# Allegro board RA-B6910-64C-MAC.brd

Outline 430 x 225 mm; copper layers: TOP, GND1, POWER1, SIG1, GND2, SIG2, GND3, SIG3, GND4, SIG4, GND5, SIG5, GND6, SIG6, GND7, SIG7, GND8, SIG8, GND9, SIG9, GND10, SIG10, GND11, POWER2, GND12, BOTTOM. Coordinates in mm from the lower left corner of the outline.
Outline path: 2,3 arc(0.59,3.59) 0,5 0,168.75 arc(0.59,170.16) 2,170.75 4.5,170.75 arc(5.21,171.04) 5.5,171.75 5.5,172.25 arc(5.21,172.96) 4.5,173.25 2,173.25 arc(0.59,173.84) 0,175.25 0,223 arc(0.59,224.41) 2,225 428,225 arc(429.41,224.41) 430,223 430,208.1 arc(429.41,206.69) 428,206.1 425.5,206.1 arc(424.79,205.81) 424.5,205.1 424.5,204.8 arc(424.79,204.09) 425.5,203.8 428,203.8 arc(429.41,203.21) 430,201.8 430,2 arc(429.41,0.59) 428,0 388,0 ; 2,3 385,3 ; 2,3 385,3 ; 385,3 arc(385.88,0.88) 388,0 ; 385,3 arc(385.88,0.88) 388,0 ; 389.3,72.5 arc(389.45,72.85) 389.8,73 392.8,73 arc(393.15,72.85) 393.3,72.5 393.3,68.5 arc(393.15,68.15) 392.8,68 389.8,68 arc(389.45,68.15) 389.3,68.5 389.3,72.5 ; 416.7,72.5 arc(416.85,72.85) 417.2,73 420.2,73 arc(420.55,72.85) 420.7,72.5 420.7,68.5 arc(420.55,68.15) 420.2,68 417.2,68 arc(416.85,68.15) 416.7,68.5 416.7,72.5

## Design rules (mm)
net group 56970_COREPLL_REFCLK_N: nets 56970_COREPLL_REFCLK_N N5117511
net group 56970_COREPLL_REFCLK_P: nets 56970_COREPLL_REFCLK_P N5117515
net group 56970_MISC_PLL_REFCLK_N: nets 56970_MISC_PLL_REFCLK_N N5121594
net group 56970_MISC_PLL_REFCLK_P: nets 56970_MISC_PLL_REFCLK_P N5121590
net group B50610_MDI_0N: nets B50610_MDI_0N B50610_MDI_1P
net group B50610_MDI_0P: nets B50610_MDI_0P B50610_MDI_1N
net group B50610_MDI_2N: nets B50610_MDI_2N B50610_MDI_3N
net group B50610_MDI_2P: nets B50610_MDI_2P B50610_MDI_3P
net group BMC_I2C_SDA: nets BMC_I2C_SDA N32265631
net group DIFFPAIR9: nets MAC_GND_SENSE MAC_VDD_SENSE
net group DIFFPAIR16: nets N32687490 N32687538
net group DIFFPAIR17: nets N32687488 N32687536
net group DIFFPAIR18: nets N32687486 N32687534
net group DIFFPAIR19: nets N32687454 N32687492
net group DIFFPAIR20: nets N32344332 N32344334
net group DIFFPAIR21: nets N32344144 N32344146
net group DIFFPAIR22: nets N32339133 N32340280
net group DIFFPAIR23: nets N32339113 N32339115
net group DIFFPAIR24: nets N32344318 N32344320
net group DIFFPAIR25: nets N32340551 N32340553
net group DIFFPAIR26: nets N32340547 N32340549
net group DIFFPAIR27: nets N32340543 N32340545
net group DIFFPAIR28: nets N5121846 N5121850
net group DIFFPAIR29: nets N6023779 N6023783
net group DIFFPAIR30: nets N6023843 N6023847
net group FC_PLL0_REFCLK_N: nets FC_PLL0_REFCLK_N N5126300
net group FC_PLL0_REFCLK_P: nets FC_PLL0_REFCLK_P N5126296
net group FC_PLL1_REFCLK_N: nets FC_PLL1_REFCLK_N N5126312
net group FC_PLL1_REFCLK_P: nets FC_PLL1_REFCLK_P N5126308
net group FC_PLL2_REFCLK_N: nets FC_PLL2_REFCLK_N N5126304
net group FC_PLL2_REFCLK_P: nets FC_PLL2_REFCLK_P N5126324
net group FC_PLL3_REFCLK_N: nets FC_PLL3_REFCLK_N N5126320
net group FC_PLL3_REFCLK_P: nets FC_PLL3_REFCLK_P N5126316
net group MC_TD1: nets MC_TDN1 MC_TDP1
net group MC_TD3: nets MC_TDN3 MC_TDP3
net group MDI_A: nets MDI_A+ MDI_A-
net group MDI_B: nets MDI_B+ MDI_B-
net group MDI_C: nets MDI_C+ MDI_C-
net group MDI_D: nets MDI_D+ MDI_D-
net group USB: nets USB0_DM USB0_DP
net group 25G: nets FC0_RDN0 FC0_RDN1 FC0_RDN2 FC0_RDN3 FC0_RDP0 FC0_RDP1 FC0_RDP2 FC0_RDP3 FC0_TDN0 FC0_TDN1 FC0_TDN2 FC0_TDN3 FC0_TDP0 FC0_TDP1 FC0_TDP2 FC0_TDP3 FC1_RDN0 FC1_RDN1 FC1_RDN2 FC1_RDN3 FC1_RDP0 FC1_RDP1 FC1_RDP2 FC1_RDP3 FC1_TDN0 FC1_TDN1 FC1_TDN2 FC1_TDN3 FC1_TDP0 FC1_TDP1 FC1_TDP2 FC1_TDP3 FC2_RDN0 FC2_RDN1 FC2_RDN2 FC2_RDN3 FC2_RDP0 FC2_RDP1 FC2_RDP2 FC2_RDP3 FC2_TDN0 FC2_TDN1 FC2_TDN2 FC2_TDN3 FC2_TDP0 FC2_TDP1 FC2_TDP2 FC2_TDP3 FC3_RDN0 FC3_RDN1 FC3_RDN2 FC3_RDN3 FC3_RDP0 FC3_RDP1 FC3_RDP2 FC3_RDP3 FC3_TDN0 FC3_TDN1 FC3_TDN2 FC3_TDN3 FC3_TDP0 FC3_TDP1 FC3_TDP2 FC3_TDP3 FC4_RDN0 FC4_RDN1 FC4_RDN2 FC4_RDN3 FC4_RDP0 FC4_RDP1 FC4_RDP2 FC4_RDP3 FC4_TDN0 FC4_TDN1 FC4_TDN2 FC4_TDN3 FC4_TDP0 FC4_TDP1 FC4_TDP2 FC4_TDP3 FC5_RDN0 FC5_RDN1 FC5_RDN2 FC5_RDN3 FC5_RDP0 FC5_RDP1 FC5_RDP2 FC5_RDP3 FC5_TDN0 FC5_TDN1 FC5_TDN2 FC5_TDN3 FC5_TDP0 FC5_TDP1 FC5_TDP2 FC5_TDP3 FC6_RDN0 FC6_RDN1 FC6_RDN2 FC6_RDN3 FC6_RDP0 FC6_RDP1 FC6_RDP2 FC6_RDP3 FC6_TDN0 FC6_TDN1 FC6_TDN2 FC6_TDN3 FC6_TDP0 FC6_TDP1 FC6_TDP2 FC6_TDP3 FC7_RDN0 FC7_RDN1 FC7_RDN2 FC7_RDN3 FC7_RDP0 FC7_RDP1 FC7_RDP2 FC7_RDP3 FC7_TDN0 FC7_TDN1 FC7_TDN2 FC7_TDN3 FC7_TDP0 FC7_TDP1 FC7_TDP2 FC7_TDP3 FC8_RDN0 FC8_RDN1 FC8_RDN2 FC8_RDN3 FC8_RDP0 FC8_RDP1 FC8_RDP2 FC8_RDP3 FC8_TDN0 FC8_TDN1 FC8_TDN2 FC8_TDN3 FC8_TDP0 FC8_TDP1 FC8_TDP2 FC8_TDP3 FC9_RDN0 FC9_RDN1 FC9_RDN2 FC9_RDN3 FC9_RDP0 FC9_RDP1 FC9_RDP2 FC9_RDP3 FC9_TDN0 FC9_TDN1 FC9_TDN2 FC9_TDN3 FC9_TDP0 FC9_TDP1 FC9_TDP2 FC9_TDP3 FC10_RDN0 FC10_RDN1 FC10_RDN2 FC10_RDN3 FC10_RDP0 FC10_RDP1 FC10_RDP2 FC10_RDP3 FC10_TDN0 FC10_TDN1 FC10_TDN2 FC10_TDN3 FC10_TDP0 FC10_TDP1 FC10_TDP2 FC10_TDP3 FC11_RDN0 FC11_RDN1 FC11_RDN2 FC11_RDN3 FC11_RDP0 FC11_RDP1 FC11_RDP2 FC11_RDP3 FC11_TDN0 FC11_TDN1 FC11_TDN2 FC11_TDN3 FC11_TDP0 FC11_TDP1 FC11_TDP2 FC11_TDP3 FC12_RDN0 FC12_RDN1 FC12_RDN2 FC12_RDN3 FC12_RDP0 FC12_RDP1 FC12_RDP2 FC12_RDP3 FC12_TDN0 FC12_TDN1 FC12_TDN2 FC12_TDN3 FC12_TDP0 FC12_TDP1 FC12_TDP2 FC12_TDP3 FC13_RDN0 FC13_RDN1 FC13_RDN2 FC13_RDN3 FC13_RDP0 FC13_RDP1 FC13_RDP2 FC13_RDP3 FC13_TDN0 FC13_TDN1 FC13_TDN2 FC13_TDN3 FC13_TDP0 FC13_TDP1 FC13_TDP2 FC13_TDP3 FC14_RDN0 FC14_RDN1 FC14_RDN2 FC14_RDN3 FC14_RDP0 FC14_RDP1 FC14_RDP2 FC14_RDP3 FC14_TDN0 FC14_TDN1 FC14_TDN2 FC14_TDN3 FC14_TDP0 FC14_TDP1 FC14_TDP2 FC14_TDP3 FC15_RDN0 FC15_RDN1 FC15_RDN2 FC15_RDN3 FC15_RDP0 FC15_RDP1 FC15_RDP2 FC15_RDP3 FC15_TDN0 FC15_TDN1 FC15_TDN2 FC15_TDN3 FC15_TDP0 FC15_TDP1 FC15_TDP2 FC15_TDP3 FC16_RDN0 FC16_RDN1 FC16_RDN2 FC16_RDN3 FC16_RDP0 FC16_RDP1 FC16_RDP2 FC16_RDP3 FC16_TDN0 FC16_TDN1 FC16_TDN2 FC16_TDN3 FC16_TDP0 FC16_TDP1 FC16_TDP2 FC16_TDP3 FC17_RDN0 FC17_RDN1 FC17_RDN2 FC17_RDN3 FC17_RDP0 FC17_RDP1 FC17_RDP2 FC17_RDP3 FC17_TDN0 FC17_TDN1 FC17_TDN2 FC17_TDN3 FC17_TDP0 FC17_TDP1 FC17_TDP2 FC17_TDP3 FC18_RDN0 FC18_RDN1 FC18_RDN2 FC18_RDN3 FC18_RDP0 FC18_RDP1 FC18_RDP2 FC18_RDP3 FC18_TDN0 FC18_TDN1 FC18_TDN2 FC18_TDN3 FC18_TDP0 FC18_TDP1 FC18_TDP2 FC18_TDP3 FC19_RDN0 FC19_RDN1 FC19_RDN2 FC19_RDN3 FC19_RDP0 FC19_RDP1 FC19_RDP2 FC19_RDP3 FC19_TDN0 FC19_TDN1 FC19_TDN2 FC19_TDN3 FC19_TDP0 FC19_TDP1 FC19_TDP2 FC19_TDP3 FC20_RDN0 FC20_RDN1 FC20_RDN2 FC20_RDN3 FC20_RDP0 FC20_RDP1 FC20_RDP2 FC20_RDP3 FC20_TDN0 FC20_TDN1 FC20_TDN2 FC20_TDN3 FC20_TDP0 FC20_TDP1 FC20_TDP2 FC20_TDP3 FC21_RDN0 FC21_RDN1 FC21_RDN2 FC21_RDN3 FC21_RDP0 FC21_RDP1 FC21_RDP2 FC21_RDP3 FC21_TDN0 FC21_TDN1 FC21_TDN2 FC21_TDN3 FC21_TDP0 FC21_TDP1 FC21_TDP2 FC21_TDP3 FC22_RDN0 FC22_RDN1 FC22_RDN2 FC22_RDN3 FC22_RDP0 FC22_RDP1 FC22_RDP2 FC22_RDP3 FC22_TDN0 FC22_TDN1 FC22_TDN2 FC22_TDN3 FC22_TDP0 FC22_TDP1 FC22_TDP2 FC22_TDP3 FC23_RDN0 FC23_RDN1 FC23_RDN2 FC23_RDN3 FC23_RDP0 FC23_RDP1 FC23_RDP2 FC23_RDP3 FC23_TDN0 FC23_TDN1 FC23_TDN2 FC23_TDN3 FC23_TDP0 FC23_TDP1 FC23_TDP2 FC23_TDP3 FC24_RDN0 FC24_RDN1 FC24_RDN2 FC24_RDN3 FC24_RDP0 FC24_RDP1 FC24_RDP2 FC24_RDP3 FC24_TDN0 FC24_TDN1 FC24_TDN2 FC24_TDN3 FC24_TDP0 FC24_TDP1 FC24_TDP2 FC24_TDP3 FC25_RDN0 FC25_RDN1 FC25_RDN2 FC25_RDN3 FC25_RDP0 FC25_RDP1 FC25_RDP2 FC25_RDP3 FC25_TDN0 FC25_TDN1 FC25_TDN2 FC25_TDN3 FC25_TDP0 FC25_TDP1 FC25_TDP2 FC25_TDP3 FC26_RDN0 FC26_RDN1 FC26_RDN2 FC26_RDN3 FC26_RDP0 FC26_RDP1 FC26_RDP2 FC26_RDP3 FC26_TDN0 FC26_TDN1 FC26_TDN2 FC26_TDN3 FC26_TDP0 FC26_TDP1 FC26_TDP2 FC26_TDP3 FC27_RDN0 FC27_RDN1 FC27_RDN2 FC27_RDN3 FC27_RDP0 FC27_RDP1 FC27_RDP2 FC27_RDP3 FC27_TDN0 FC27_TDN1 FC27_TDN2 FC27_TDN3 FC27_TDP0 FC27_TDP1 FC27_TDP2 FC27_TDP3 FC28_RDN0 FC28_RDN1 FC28_RDN2 FC28_RDN3 FC28_RDP0 FC28_RDP1 FC28_RDP2 FC28_RDP3 FC28_TDN0 FC28_TDN1 FC28_TDN2 FC28_TDN3 FC28_TDP0 FC28_TDP1 FC28_TDP2 FC28_TDP3 FC29_RDN0 FC29_RDN1 FC29_RDN2 FC29_RDN3 FC29_RDP0 FC29_RDP1 FC29_RDP2 FC29_RDP3 FC29_TDN0 FC29_TDN1 FC29_TDN2 FC29_TDN3 FC29_TDP0 FC29_TDP1 FC29_TDP2 FC29_TDP3 FC30_RDN0 FC30_RDN1 FC30_RDN2 FC30_RDN3 FC30_RDP0 FC30_RDP1 FC30_RDP2 FC30_RDP3 FC30_TDN0 FC30_TDN1 FC30_TDN2 FC30_TDN3 FC30_TDP0 FC30_TDP1 FC30_TDP2 FC30_TDP3 FC31_RDN0 FC31_RDN1 FC31_RDN2 FC31_RDN3 FC31_RDP0 FC31_RDP1 FC31_RDP2 FC31_RDP3 FC31_TDN0 FC31_TDN1 FC31_TDN2 FC31_TDN3 FC31_TDP0 FC31_TDP1 FC31_TDP2 FC31_TDP3 FC32_RDN0 FC32_RDN1 FC32_RDN2 FC32_RDN3 FC32_RDP0 FC32_RDP1 FC32_RDP2 FC32_RDP3 FC32_TDN0 FC32_TDN1 FC32_TDN2 FC32_TDN3 FC32_TDP0 FC32_TDP1 FC32_TDP2 FC32_TDP3 FC33_RDN0 FC33_RDN1 FC33_RDN2 FC33_RDN3 FC33_RDP0 FC33_RDP1 FC33_RDP2 FC33_RDP3 FC33_TDN0 FC33_TDN1 FC33_TDN2 FC33_TDN3 FC33_TDP0 FC33_TDP1 FC33_TDP2 FC33_TDP3 FC34_RDN0 FC34_RDN1 FC34_RDN2 FC34_RDN3 FC34_RDP0 FC34_RDP1 FC34_RDP2 FC34_RDP3 FC34_TDN0 FC34_TDN1 FC34_TDN2 FC34_TDN3 FC34_TDP0 FC34_TDP1 FC34_TDP2 FC34_TDP3 FC35_RDN0 FC35_RDN1 FC35_RDN2 FC35_RDN3 FC35_RDP0 FC35_RDP1 FC35_RDP2 FC35_RDP3 FC35_TDN0 FC35_TDN1 FC35_TDN2 FC35_TDN3 FC35_TDP0 FC35_TDP1 FC35_TDP2 FC35_TDP3 FC36_RDN0 FC36_RDN1 FC36_RDN2 FC36_RDN3 FC36_RDP0 FC36_RDP1 FC36_RDP2 FC36_RDP3 FC36_TDN0 FC36_TDN1 FC36_TDN2 FC36_TDN3 FC36_TDP0 FC36_TDP1 FC36_TDP2 FC36_TDP3 FC37_RDN0 FC37_RDN1 FC37_RDN2 FC37_RDN3 FC37_RDP0 FC37_RDP1 FC37_RDP2 FC37_RDP3 FC37_TDN0 FC37_TDN1 FC37_TDN2 FC37_TDN3 FC37_TDP0 FC37_TDP1 FC37_TDP2 FC37_TDP3 FC38_RDN0 FC38_RDN1 FC38_RDN2 FC38_RDN3 FC38_RDP0 FC38_RDP1 FC38_RDP2 FC38_RDP3 FC38_TDN0 FC38_TDN1 FC38_TDN2 FC38_TDN3 FC38_TDP0 FC38_TDP1 FC38_TDP2 FC38_TDP3 FC39_RDN0 FC39_RDN1 FC39_RDN2 FC39_RDN3 FC39_RDP0 FC39_RDP1 FC39_RDP2 FC39_RDP3 FC39_TDN0 FC39_TDN1 FC39_TDN2 FC39_TDN3 FC39_TDP0 FC39_TDP1 FC39_TDP2 FC39_TDP3 FC40_RDN0 FC40_RDN1 FC40_RDN2 FC40_RDN3 FC40_RDP0 FC40_RDP1 FC40_RDP2 FC40_RDP3 FC40_TDN0 FC40_TDN1 FC40_TDN2 FC40_TDN3 FC40_TDP0 FC40_TDP1 FC40_TDP2 FC40_TDP3 FC41_RDN0 FC41_RDN1 FC41_RDN2 FC41_RDN3 FC41_RDP0 FC41_RDP1 FC41_RDP2 FC41_RDP3 FC41_TDN0 FC41_TDN1 FC41_TDN2 FC41_TDN3 FC41_TDP0 FC41_TDP1 FC41_TDP2 FC41_TDP3 FC42_RDN0 FC42_RDN1 FC42_RDN2 FC42_RDN3 FC42_RDP0 FC42_RDP1 FC42_RDP2 FC42_RDP3 FC42_TDN0 FC42_TDN1 FC42_TDN2 FC42_TDN3 FC42_TDP0 FC42_TDP1 FC42_TDP2 FC42_TDP3 FC43_RDN0 FC43_RDN1 FC43_RDN2 FC43_RDN3 FC43_RDP0 FC43_RDP1 FC43_RDP2 FC43_RDP3 FC43_TDN0 FC43_TDN1 FC43_TDN2 FC43_TDN3 FC43_TDP0 FC43_TDP1 FC43_TDP2 FC43_TDP3 FC44_RDN0 FC44_RDN1 FC44_RDN2 FC44_RDN3 FC44_RDP0 FC44_RDP1 FC44_RDP2 FC44_RDP3 FC44_TDN0 FC44_TDN1 FC44_TDN2 FC44_TDN3 FC44_TDP0 FC44_TDP1 FC44_TDP2 FC44_TDP3 FC45_RDN0 FC45_RDN1 FC45_RDN2 FC45_RDN3 FC45_RDP0 FC45_RDP1 FC45_RDP2 FC45_RDP3 FC45_TDN0 FC45_TDN1 FC45_TDN2 FC45_TDN3 FC45_TDP0 FC45_TDP1 FC45_TDP2 FC45_TDP3 FC46_RDN0 FC46_RDN1 FC46_RDN2 FC46_RDN3 FC46_RDP0 FC46_RDP1 FC46_RDP2 FC46_RDP3 FC46_TDN0 FC46_TDN1 FC46_TDN2 FC46_TDN3 FC46_TDP0 FC46_TDP1 FC46_TDP2 FC46_TDP3 FC47_RDN0 FC47_RDN1 FC47_RDN2 FC47_RDN3 FC47_RDP0 FC47_RDP1 FC47_RDP2 FC47_RDP3 FC47_TDN0 FC47_TDN1 FC47_TDN2 FC47_TDN3 FC47_TDP0 FC47_TDP1 FC47_TDP2 FC47_TDP3 FC48_RDN0 FC48_RDN1 FC48_RDN2 FC48_RDN3 FC48_RDP0 FC48_RDP1 FC48_RDP2 FC48_RDP3 FC48_TDN0 FC48_TDN1 FC48_TDN2 FC48_TDN3 FC48_TDP0 FC48_TDP1 FC48_TDP2 FC48_TDP3 FC49_RDN0 FC49_RDN1 FC49_RDN2 FC49_RDN3 FC49_RDP0 FC49_RDP1 FC49_RDP2 FC49_RDP3 FC49_TDN0 FC49_TDN1 FC49_TDN2 FC49_TDN3 FC49_TDP0 FC49_TDP1 FC49_TDP2 FC49_TDP3 FC50_RDN0 FC50_RDN1 FC50_RDN2 FC50_RDN3 FC50_RDP0 FC50_RDP1 FC50_RDP2 FC50_RDP3 FC50_TDN0 FC50_TDN1 FC50_TDN2 FC50_TDN3 FC50_TDP0 FC50_TDP1 FC50_TDP2 FC50_TDP3 FC51_RDN0 FC51_RDN1 FC51_RDN2 FC51_RDN3 FC51_RDP0 FC51_RDP1 FC51_RDP2 FC51_RDP3 FC51_TDN0 FC51_TDN1 FC51_TDN2 FC51_TDN3 FC51_TDP0 FC51_TDP1 FC51_TDP2 FC51_TDP3 FC52_RDN0 FC52_RDN1 FC52_RDN2 FC52_RDN3 FC52_RDP0 FC52_RDP1 FC52_RDP2 FC52_RDP3 FC52_TDN0 FC52_TDN1 FC52_TDN2 FC52_TDN3 FC52_TDP0 FC52_TDP1 FC52_TDP2 FC52_TDP3 FC53_RDN0 FC53_RDN1 FC53_RDN2 FC53_RDN3 FC53_RDP0 FC53_RDP1 FC53_RDP2 FC53_RDP3 FC53_TDN0 FC53_TDN1 FC53_TDN2 FC53_TDN3 FC53_TDP0 FC53_TDP1 FC53_TDP2 FC53_TDP3 FC54_RDN0 FC54_RDN1 FC54_RDN2 FC54_RDN3 FC54_RDP0 FC54_RDP1 FC54_RDP2 FC54_RDP3 FC54_TDN0 FC54_TDN1 FC54_TDN2 FC54_TDN3 FC54_TDP0 FC54_TDP1 FC54_TDP2 FC54_TDP3 FC55_RDN0 FC55_RDN1 FC55_RDN2 FC55_RDN3 FC55_RDP0 FC55_RDP1 FC55_RDP2 FC55_RDP3 FC55_TDN0 FC55_TDN1 FC55_TDN2 FC55_TDN3 FC55_TDP0 FC55_TDP1 FC55_TDP2 FC55_TDP3 FC56_RDN0 FC56_RDN1 FC56_RDN2 FC56_RDN3 FC56_RDP0 FC56_RDP1 FC56_RDP2 FC56_RDP3 FC56_TDN0 FC56_TDN1 FC56_TDN2 FC56_TDN3 FC56_TDP0 FC56_TDP1 FC56_TDP2 FC56_TDP3 FC57_RDN0 FC57_RDN1 FC57_RDN2 FC57_RDN3 FC57_RDP0 FC57_RDP1 FC57_RDP2 FC57_RDP3 FC57_TDN0 FC57_TDN1 FC57_TDN2 FC57_TDN3 FC57_TDP0 FC57_TDP1 FC57_TDP2 FC57_TDP3 FC58_RDN0 FC58_RDN1 FC58_RDN2 FC58_RDN3 FC58_RDP0 FC58_RDP1 FC58_RDP2 FC58_RDP3 FC58_TDN0 FC58_TDN1 FC58_TDN2 FC58_TDN3 FC58_TDP0 FC58_TDP1 FC58_TDP2 FC58_TDP3 FC59_RDN0 FC59_RDN1 FC59_RDN2 FC59_RDN3 FC59_RDP0 FC59_RDP1 FC59_RDP2 FC59_RDP3 FC59_TDN0 FC59_TDN1 FC59_TDN2 FC59_TDN3 FC59_TDP0 FC59_TDP1 FC59_TDP2 FC59_TDP3 FC60_RDN0 FC60_RDN1 FC60_RDN2 FC60_RDN3 FC60_RDP0 FC60_RDP1 FC60_RDP2 FC60_RDP3 FC60_TDN0 FC60_TDN1 FC60_TDN2 FC60_TDN3 FC60_TDP0 FC60_TDP1 FC60_TDP2 FC60_TDP3 FC61_RDN0 FC61_RDN1 FC61_RDN2 FC61_RDN3 FC61_RDP0 FC61_RDP1 FC61_RDP2 FC61_RDP3 FC61_TDN0 FC61_TDN1 FC61_TDN2 FC61_TDN3 FC61_TDP0 FC61_TDP1 FC61_TDP2 FC61_TDP3 FC62_RDN0 FC62_RDN1 FC62_RDN2 FC62_RDN3 FC62_RDP0 FC62_RDP1 FC62_RDP2 FC62_RDP3 FC62_TDN0 FC62_TDN1 FC62_TDN2 FC62_TDN3 FC62_TDP0 FC62_TDP1 FC62_TDP2 FC62_TDP3 FC63_RDN0 FC63_RDN1 FC63_RDN2 FC63_RDN3 FC63_RDP0 FC63_RDP1 FC63_RDP2 FC63_RDP3 FC63_TDN0 FC63_TDN1 FC63_TDN2 FC63_TDN3 FC63_TDP0 FC63_TDP1 FC63_TDP2 FC63_TDP3 FC_LOS0 FC_LOS1 FC_LOS2 FC_LOS3 FC_LOS4 FC_LOS5 FC_LOS6 FC_LOS7 FC_LOS8 FC_LOS9 FC_LOS10 FC_LOS11 FC_LOS12 FC_LOS13 FC_LOS14 FC_LOS15 FC_LOS16 FC_LOS17 FC_LOS18 FC_LOS19 FC_LOS20 FC_LOS21 FC_LOS22 FC_LOS23 FC_LOS24 FC_LOS25 FC_LOS26 FC_LOS27 FC_LOS28 FC_LOS29 FC_LOS30 FC_LOS31 FC_LOS32 FC_LOS33 FC_LOS34 FC_LOS35 FC_LOS36 FC_LOS37 FC_LOS38 FC_LOS39 FC_LOS40 FC_LOS41 FC_LOS42 FC_LOS43 FC_LOS44 FC_LOS45 FC_LOS46 FC_LOS47 FC_LOS48 FC_LOS49 FC_LOS50 FC_LOS51 FC_LOS52 FC_LOS53 FC_LOS54 FC_LOS55 FC_LOS56 FC_LOS57 FC_LOS58 FC_LOS59 FC_LOS60 FC_LOS61 FC_LOS62 FC_LOS63
net group CLK-DIFF: nets 56970_PCIE_PLL_REFCLK_N 56970_PCIE_PLL_REFCLK_P MASTER_CPLD_CLK_N MASTER_CPLD_CLK_P SECOND_CPLD_CLK_N SECOND_CPLD_CLK_P
net group CPU_I2C_SDA: nets CPU_I2C_SDA N24037211 N24037257 N24037299 N24037469 N24044300 N24045758 N24045803 N24045845
net group KR: nets MAC_MC_RDN0 MAC_MC_RDN2 MAC_MC_RDP0 MAC_MC_RDP2 MC_RDN0 MC_RDN2 MC_RDP0 MC_RDP2 MC_TDN0 MC_TDN2 MC_TDP0 MC_TDP2
net group PCIE: nets MAC_PCIE_RXN0 MAC_PCIE_RXN1 MAC_PCIE_RXN2 MAC_PCIE_RXN3 MAC_PCIE_RXP0 MAC_PCIE_RXP1 MAC_PCIE_RXP2 MAC_PCIE_RXP3 MAC_PCIE_TXN0 MAC_PCIE_TXN1 MAC_PCIE_TXN2 MAC_PCIE_TXN3 MAC_PCIE_TXP0 MAC_PCIE_TXP1 MAC_PCIE_TXP2 MAC_PCIE_TXP3 N26921640 N26921643 N26921646 N26921649 N26921652 N26921655 N26921658 N26921661
net group VDD1.2V: nets N24368040
nets with their own width: min track width 0.381; nets GND

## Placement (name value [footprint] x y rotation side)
C1  X  [C0402]  260.29 170.3 90 top
C2  0.1uF/25V  [C0402]  205.07 156.35 90 bottom
C3  0.1uF/25V  [C0402]  204.05 158.35 90 bottom
C4  0.1uF/25V  [C0402]  205.04 154.35 270 bottom
C5  103  [C0402]  179.13 191.13 270 top
C6  103  [C0402]  178.12 191.13 270 top
C7  103  [C0402]  182.56 186.81 270 top
C8  103  [C0402]  181.55 186.81 270 top
C9  103  [C0402]  250 138.43 180 top
C10  103  [C0402]  250 137.28 180 top
C11  104  [C0603]  37.27 205.99 90 bottom
C12  10uF/25V  [C0805]  17.84 205.74 90 bottom
C13  1uF/25V  [C0805]  35.12 205.86 90 bottom
C14  33uF/10V  [C1206]  394.4 24.76 0 top
C17  103  [C0402]  155.51 128.27 0 top
C18  103  [C0402]  155.51 129.28 0 top
C19  103  [C0402]  247.84 143.51 270 top
C20  103  [C0402]  246.82 143.51 270 top
C21  5.6P  [C0402]  403.16 194.43 0 top
C27  0.1uF/25V  [C0402]  205.07 158.35 90 bottom
C28  0.1uF/25V  [C0402]  210.07 158.34 90 bottom
C29  0.1uF/25V  [C0402]  205.56 120.84 180 bottom
C30  0.1uF/25V  [C0402]  207.55 123.82 180 bottom
C49  0.1uF/25V  [C0402]  215.56 159.85 0 bottom
C50  0.1uF/25V  [C0402]  215.54 122.85 0 bottom
C51  0.1uF/25V  [C0402]  215.55 115.81 180 bottom
C52  0.1uF/25V  [C0402]  187.05 154.33 270 bottom
C53  0.1uF/25V  [C0402]  185.05 156.33 270 bottom
C54  1uF/25V  [C0402]  215.55 114.81 180 bottom
C74  0.1uF/25V  [C0402]  219.65 200.15 90 top
C75  22uF/6.3V  [C0603]  152.59 133.09 270 top
C76  0.1uF/25V  [C0402]  178.63 137.72 0 bottom
C79  22uF/6.3V  [C0603]  176.72 191.64 90 top
C80  0.1uF/25V  [C0402]  199.54 157.83 0 bottom
C82  0.1uF/25V  [C0402]  235.65 145.54 90 top
C83  22uF/6.3V  [C0603]  235.65 137.79 270 top
C84  0.1uF/25V  [C0402]  215.55 138.82 180 bottom
C86  0.1uF/25V  [C0402]  161.86 191.64 270 top
C87  22uF/6.3V  [C0603]  219.65 192.66 270 top
C88  0.1uF/25V  [C0402]  204.05 156.35 90 bottom
C90  0.1uF/25V  [C0402]  181.29 178.43 270 top
C91  22uF/6.3V  [C0603]  185.48 179.07 90 top
C92  0.1uF/25V  [C0402]  178.57 153.85 180 bottom
C93  0.1uF/25V  [C0402]  195.55 151.82 180 bottom
C94  0.1uF/25V  [C0402]  193.55 146.82 180 bottom
C95  0.1uF/25V  [C0402]  217.57 152.83 0 bottom
C96  0.1uF/25V  [C0402]  178.56 128.83 0 bottom
C97  0.1uF/25V  [C0402]  215.55 129.82 180 bottom
C98  0.1uF/25V  [C0402]  197.54 127.83 180 bottom
C99  0.1uF/25V  [C0402]  197.54 128.83 180 bottom
C100  0.1uF/25V  [C0402]  185.36 198.25 90 top
C101  22uF/6.3V  [C0603]  185.1 192.4 270 top
C102  0.1uF/25V  [C0402]  191.55 153.82 180 bottom
C103  0.1uF/25V  [C0402]  189.05 154.33 90 bottom
C108  102  [C0402]  387.92 213.61 270 top
C109  0.1uF/25V  [C0402]  389.14 213.61 270 top
C110  33uF/10V  [C1206]  384.29 212.94 270 bottom
C111  0.1uF/25V  [C0402]  423.1 129.16 0 top
C112  0.1uF/25V  [C0402]  57.21 106.04 0 top
C113  0.1uF/25V  [C0402]  22.54 100.96 0 top
C114  0.1uF/25V  [C0402]  265.29 181.4 270 top
C115  0.1uF/25V  [C0402]  411.34 116.58 180 bottom
C116  0.1uF/25V  [C0402]  10.66 100.96 180 bottom
C117  0.1uF/25V  [C0402]  45.33 106.04 180 bottom
C118  0.1uF/25V  [C0402]  411.34 128.1 180 bottom
C119  0.1uF/25V  [C0402]  423.1 116.58 0 top
C203  22uF/6.3V  [C0603]  236.66 111 180 top
C204  0.1uF/25V  [C0402]  211.56 110.86 180 bottom
C205  0.1uF/25V  [C0402]  205.57 107.84 180 bottom
C206  0.1uF/25V  [C0402]  205.57 106.84 180 bottom
C207  0.1uF/25V  [C0402]  229.56 119.83 0 bottom
C209  0.1uF/25V  [C0402]  230.57 109.84 0 bottom
C212  0.1uF/25V  [C0402]  227.54 125.85 0 bottom
C213  0.1uF/25V  [C0402]  199.56 110.86 0 bottom
C215  0.1uF/25V  [C0402]  199.56 109.84 180 bottom
C216  0.1uF/25V  [C0402]  226.53 115.84 0 bottom
C219  0.1uF/25V  [C0402]  229.55 133.82 0 bottom
C221  0.1uF/25V  [C0402]  231.2 177.54 270 top
C226  0.1uF/25V  [C0402]  207.02 170.38 270 bottom
C227  0.1uF/25V  [C0402]  211.06 167.33 270 bottom
C247  0.1uF/25V  [C0402]  199.03 170.33 270 bottom
C274  22uF/6.3V  [C0603]  153.61 173.06 90 top
C275  0.1uF/25V  [C0402]  182.05 154.33 90 bottom
C276  0.1uF/25V  [C0402]  155.26 165.99 90 top
C277  22uF/6.3V  [C0603]  157.16 158.11 270 top
C278  0.1uF/25V  [C0402]  181.54 152.83 0 bottom
C279  0.1uF/25V  [C0402]  154.24 165.99 90 top
C280  22uF/6.3V  [C0603]  154.88 158.11 270 top
C281  0.1uF/25V  [C0402]  181.54 149.83 0 bottom
C282  0.1uF/25V  [C0402]  141.67 150.31 90 bottom
C283  22uF/6.3V  [C0603]  157.16 145.79 270 top
C284  0.1uF/25V  [C0402]  181.53 146.83 180 bottom
C297  10uF/25V  [C0805]  253.84 209.78 270 top
C298  10uF/25V  [C0805]  256.38 209.78 270 top
C299  104  [C0603]  258.38 209.67 270 top
C300  104  [C0603]  257.54 216.1 90 bottom
C301  X  [C0603]  266.94 215.31 180 top
C302  1uF/25V  [C0402]  267.02 216.84 0 top
C303  103  [C0402]  267.02 218.11 0 top
C305  22uF/6.3V  [C0603]  240.37 208.56 270 top
C306  22uF/6.3V  [C0603]  238.85 208.56 270 top
C307  1uF/25V  [C0402]  242.89 208.53 270 top
C308  0.1uF/25V  [C0402]  241.74 208.53 270 top
C349  22uF/6.3V  [C0603]  214.82 192.66 270 top
C350  0.1uF/25V  [C0402]  213.58 153.85 0 bottom
C351  0.1uF/25V  [C0402]  222.06 200.15 90 top
C352  22uF/6.3V  [C0603]  229.3 192.66 270 top
C389  0.1uF/25V  [C0402]  170.53 157.84 0 bottom
C391  0.1uF/25V  [C0402]  168.52 160.84 0 bottom
C393  0.1uF/25V  [C0402]  168.52 156.84 180 bottom
C395  0.1uF/25V  [C0402]  168.52 158.85 0 bottom
C396  0.1uF/25V  [C0402]  176.58 157.84 0 bottom
C397  0.1uF/25V  [C0402]  177.55 154.84 0 bottom
C398  0.1uF/25V  [C0402]  172.53 157.84 0 bottom
C399  0.1uF/25V  [C0402]  170.52 158.85 0 bottom
C400  0.1uF/25V  [C0402]  174.53 160.84 0 bottom
C401  0.1uF/25V  [C0402]  172.53 160.84 0 bottom
C402  0.1uF/25V  [C0402]  166.56 154.86 0 bottom
C403  0.1uF/25V  [C0402]  171.54 151.82 0 bottom
C404  0.1uF/25V  [C0402]  168.57 154.84 0 bottom
C405  0.1uF/25V  [C0402]  174.53 157.84 0 bottom
C406  0.1uF/25V  [C0402]  170.57 154.84 0 bottom
C407  0.1uF/25V  [C0402]  183.06 160.32 270 bottom
C408  0.1uF/25V  [C0402]  165.57 152.83 180 bottom
C409  0.1uF/25V  [C0402]  172.58 154.85 0 bottom
C410  0.1uF/25V  [C0402]  187.04 161.36 90 bottom
C411  0.1uF/25V  [C0402]  189.55 160.83 0 bottom
C412  0.1uF/25V  [C0402]  192.56 159.86 0 bottom
C413  0.1uF/25V  [C0402]  176.58 160.84 0 bottom
C414  0.1uF/25V  [C0402]  141.77 162.51 90 bottom
C415  22uF/6.3V  [C0603]  154.98 157.53 0 bottom
C416  0.1uF/25V  [C0402]  186.04 161.36 270 bottom
C417  0.1uF/25V  [C0402]  186.07 164.29 90 bottom
C418  0.1uF/25V  [C0402]  187.57 166.85 0 bottom
C419  0.1uF/25V  [C0402]  190.58 164.83 0 bottom
C420  0.1uF/25V  [C0402]  166.54 166.86 0 bottom
C421  0.1uF/25V  [C0402]  166.56 162.84 0 bottom
C422  0.1uF/25V  [C0402]  165.54 164.84 0 bottom
C423  0.1uF/25V  [C0402]  183.05 164.32 270 bottom
C424  0.1uF/25V  [C0402]  183.05 162.32 90 bottom
C425  0.1uF/25V  [C0402]  183.06 166.32 90 bottom
C426  0.1uF/25V  [C0402]  180.05 162.33 90 bottom
C427  0.1uF/25V  [C0402]  181.04 164.34 90 bottom
C428  0.1uF/25V  [C0402]  180.04 167.36 90 bottom
C429  0.1uF/25V  [C0402]  179.04 162.32 90 bottom
C430  0.1uF/25V  [C0402]  179.04 164.33 90 bottom
C431  0.1uF/25V  [C0402]  179.05 167.33 90 bottom
C432  0.1uF/25V  [C0402]  176.56 165.86 0 bottom
C433  0.1uF/25V  [C0402]  173.56 164.82 0 bottom
C434  0.1uF/25V  [C0402]  176.56 164.83 0 bottom
C435  0.1uF/25V  [C0402]  192.56 162.86 0 bottom
C436  0.1uF/25V  [C0402]  196.04 164.35 90 bottom
C437  0.1uF/25V  [C0402]  189.05 162.34 90 bottom
C438  0.1uF/25V  [C0402]  192.56 165.86 0 bottom
C439  0.1uF/25V  [C0402]  192.58 164.84 0 bottom
C440  0.1uF/25V  [C0402]  189.08 164.37 90 bottom
C443  0.1uF/25V  [C0402]  184.05 172.33 90 bottom
C444  0.1uF/25V  [C0402]  173.56 167.83 0 bottom
C445  0.1uF/25V  [C0402]  195.05 167.36 270 bottom
C446  0.1uF/25V  [C0402]  194.04 168.33 90 bottom
C447  0.1uF/25V  [C0402]  196.05 167.36 270 bottom
C448  0.1uF/25V  [C0402]  191.55 167.87 0 bottom
C449  0.1uF/25V  [C0402]  186.07 172.36 90 bottom
C450  0.1uF/25V  [C0402]  168.56 168.83 0 bottom
C451  0.1uF/25V  [C0402]  190.06 170.33 270 bottom
C452  0.1uF/25V  [C0402]  167.58 170.84 180 bottom
C453  0.1uF/25V  [C0402]  169.57 166.84 0 bottom
C454  0.1uF/25V  [C0402]  168.53 171.84 0 bottom
C455  0.1uF/25V  [C0402]  176.03 171.34 270 bottom
C456  0.1uF/25V  [C0402]  176.58 168.84 0 bottom
C457  0.1uF/25V  [C0402]  177.04 171.32 270 bottom
C458  0.1uF/25V  [C0402]  178.58 172.86 0 bottom
C459  0.1uF/25V  [C0402]  174.07 171.32 270 bottom
C460  0.1uF/25V  [C0402]  176.56 167.83 0 bottom
C461  0.1uF/25V  [C0402]  182.05 169.36 90 bottom
C462  0.1uF/25V  [C0402]  184.07 169.35 90 bottom
C463  0.1uF/25V  [C0402]  190.06 167.36 270 bottom
C464  0.1uF/25V  [C0402]  170.55 171.85 180 bottom
C465  0.1uF/25V  [C0402]  172.55 171.85 0 bottom
C466  0.1uF/25V  [C0402]  173.58 168.84 0 bottom
C467  0.1uF/25V  [C0402]  188.05 171.32 90 bottom
C468  0.1uF/25V  [C0402]  140.75 124.81 270 bottom
C469  22uF/6.3V  [C0603]  148.02 118.23 270 top
C470  0.1uF/25V  [C0402]  179.04 106.36 90 bottom
C471  0.1uF/25V  [C0402]  176.64 105.78 0 bottom
C472  0.1uF/25V  [C0402]  174.64 105.78 0 bottom
C473  0.1uF/25V  [C0402]  171.64 105.78 0 bottom
C474  0.1uF/25V  [C0402]  183.53 111.86 180 bottom
C475  0.1uF/25V  [C0402]  191.54 109.84 0 bottom
C476  0.1uF/25V  [C0402]  189.53 106.84 0 bottom
C477  0.1uF/25V  [C0402]  189.53 107.84 0 bottom
C478  0.1uF/25V  [C0402]  185.54 112.86 180 bottom
C479  0.1uF/25V  [C0402]  185.53 107.84 0 bottom
C480  0.1uF/25V  [C0402]  169.55 109.82 0 bottom
C481  0.1uF/25V  [C0402]  168.59 105.03 270 bottom
C482  0.1uF/25V  [C0402]  168.58 111.84 0 bottom
C483  0.1uF/25V  [C0402]  168.52 107.83 180 bottom
C484  0.1uF/25V  [C0402]  185.53 106.84 0 bottom
C485  0.1uF/25V  [C0402]  183.52 109.86 0 bottom
C486  0.1uF/25V  [C0402]  183.53 110.86 180 bottom
C487  0.1uF/25V  [C0402]  176.58 111.84 0 bottom
C488  0.1uF/25V  [C0402]  176.56 108.85 0 bottom
C489  0.1uF/25V  [C0402]  179.53 109.85 0 bottom
C490  0.1uF/25V  [C0402]  195.54 110.84 0 bottom
C491  0.1uF/25V  [C0402]  195.54 109.85 0 bottom
C492  0.1uF/25V  [C0402]  191.54 110.84 0 bottom
C493  0.1uF/25V  [C0402]  174.56 108.85 0 bottom
C494  0.1uF/25V  [C0402]  171.56 108.83 0 bottom
C495  0.1uF/25V  [C0402]  140.96 119.53 270 bottom
C496  22uF/6.3V  [C0603]  150.94 118.23 270 top
C497  0.1uF/25V  [C0402]  170.53 114.8 0 bottom
C498  0.1uF/25V  [C0402]  172.56 114.83 0 bottom
C499  0.1uF/25V  [C0402]  164.56 115.82 180 bottom
C500  0.1uF/25V  [C0402]  183.55 114.83 0 bottom
C501  0.1uF/25V  [C0402]  183.55 115.83 0 bottom
C502  0.1uF/25V  [C0402]  165.56 117.87 0 bottom
C503  0.1uF/25V  [C0402]  189.55 115.86 180 bottom
C504  0.1uF/25V  [C0402]  195.56 116.84 0 bottom
C505  0.1uF/25V  [C0402]  195.56 118.84 0 bottom
C506  0.1uF/25V  [C0402]  191.55 112.83 180 bottom
C507  0.1uF/25V  [C0402]  165.54 111.83 0 bottom
C508  0.1uF/25V  [C0402]  165.56 113.83 0 bottom
C509  0.1uF/25V  [C0402]  185.53 113.85 180 bottom
C510  0.1uF/25V  [C0402]  170.58 111.84 180 bottom
C511  0.1uF/25V  [C0402]  172.58 111.84 0 bottom
C512  0.1uF/25V  [C0402]  174.57 114.84 0 bottom
C513  0.1uF/25V  [C0402]  176.58 114.84 0 bottom
C514  0.1uF/25V  [C0402]  174.58 111.84 0 bottom
C515  0.1uF/25V  [C0402]  166.56 115.82 0 bottom
C516  0.1uF/25V  [C0402]  189.55 113.86 180 bottom
C517  0.1uF/25V  [C0402]  191.55 115.86 180 bottom
C518  0.1uF/25V  [C0402]  189.52 112.83 180 bottom
C519  0.1uF/25V  [C0402]  191.55 113.86 180 bottom
C520  0.1uF/25V  [C0402]  187.55 115.83 0 bottom
C521  0.1uF/25V  [C0402]  189.54 114.84 180 bottom
C522  0.1uF/25V  [C0402]  140.96 134.06 90 bottom
C523  22uF/6.3V  [C0603]  150.3 133.09 90 top
C524  0.1uF/25V  [C0402]  174.56 120.85 0 bottom
C525  0.1uF/25V  [C0402]  172.56 120.85 0 bottom
C526  0.1uF/25V  [C0402]  171.06 117.32 270 bottom
C527  0.1uF/25V  [C0402]  177.08 120.34 270 bottom
C528  0.1uF/25V  [C0402]  168.52 121.84 180 bottom
C529  0.1uF/25V  [C0402]  172.56 126.85 0 bottom
C530  0.1uF/25V  [C0402]  168.53 119.85 180 bottom
C531  0.1uF/25V  [C0402]  167.55 123.83 180 bottom
C532  0.1uF/25V  [C0402]  165.54 125.85 0 bottom
C533  0.1uF/25V  [C0402]  168.56 117.86 0 bottom
C534  0.1uF/25V  [C0402]  165.56 123.86 0 bottom
C535  0.1uF/25V  [C0402]  177.05 127.35 90 bottom
C536  0.1uF/25V  [C0402]  176.57 117.83 0 bottom
C537  0.1uF/25V  [C0402]  172.56 121.87 0 bottom
C538  0.1uF/25V  [C0402]  174.56 117.85 0 bottom
C539  0.1uF/25V  [C0402]  183.55 117.83 0 bottom
C540  0.1uF/25V  [C0402]  173.06 117.32 270 bottom
C541  0.1uF/25V  [C0402]  174.56 126.85 0 bottom
C542  0.1uF/25V  [C0402]  189.55 117.86 180 bottom
C543  0.1uF/25V  [C0402]  191.55 117.86 180 bottom
C544  0.1uF/25V  [C0402]  175.53 123.85 0 bottom
C545  0.1uF/25V  [C0402]  177.53 123.82 0 bottom
C546  0.1uF/25V  [C0402]  170.55 123.82 180 bottom
C547  0.1uF/25V  [C0402]  172.56 123.82 0 bottom
C548  0.1uF/25V  [C0402]  187.55 117.83 0 bottom
C551  0.1uF/25V  [C0402]  166.56 127.83 0 bottom
C552  0.1uF/25V  [C0402]  165.56 129.85 0 bottom
C553  0.1uF/25V  [C0402]  168.57 129.84 0 bottom
C554  0.1uF/25V  [C0402]  175.58 135.84 0 bottom
C555  0.1uF/25V  [C0402]  177.58 135.84 0 bottom
C556  0.1uF/25V  [C0402]  168.54 131.82 180 bottom
C557  0.1uF/25V  [C0402]  171.56 135.86 180 bottom
C558  0.1uF/25V  [C0402]  170.54 126.84 0 bottom
C559  0.1uF/25V  [C0402]  174.56 133.86 0 bottom
C560  0.1uF/25V  [C0402]  172.53 130.85 0 bottom
C561  0.1uF/25V  [C0402]  171.54 129.84 0 bottom
C562  0.1uF/25V  [C0402]  172.53 139.7 0 bottom
C563  0.1uF/25V  [C0402]  165.54 137.82 0 bottom
C564  0.1uF/25V  [C0402]  165.56 135.84 0 bottom
C565  0.1uF/25V  [C0402]  168.56 135.85 0 bottom
C566  0.1uF/25V  [C0402]  168.56 133.83 180 bottom
C567  0.1uF/25V  [C0402]  172.58 140.84 0 bottom
C568  0.1uF/25V  [C0402]  170.57 140.84 0 bottom
C569  0.1uF/25V  [C0402]  173.58 135.84 0 bottom
C570  0.1uF/25V  [C0402]  174.56 132.84 0 bottom
C571  0.1uF/25V  [C0402]  172.53 132.84 0 bottom
C572  0.1uF/25V  [C0402]  171.56 133.85 0 bottom
C573  0.1uF/25V  [C0402]  176.54 129.84 0 bottom
C574  0.1uF/25V  [C0402]  174.54 129.84 0 bottom
C575  0.1uF/25V  [C0402]  176.57 132.84 0 bottom
C576  0.1uF/25V  [C0402]  249.97 113.74 90 bottom
C577  22uF/6.3V  [C0603]  236.56 107.96 180 bottom
C578  0.1uF/25V  [C0402]  209.05 106.32 270 bottom
C579  0.1uF/25V  [C0402]  195.54 107.85 180 bottom
C580  0.1uF/25V  [C0402]  215.02 107.34 90 bottom
C581  0.1uF/25V  [C0402]  213.05 107.31 270 bottom
C582  0.1uF/25V  [C0402]  211.05 107.31 270 bottom
C583  0.1uF/25V  [C0402]  199.56 107.84 0 bottom
C584  0.1uF/25V  [C0402]  208.53 109.84 0 bottom
C585  0.1uF/25V  [C0402]  226.63 104.9 0 bottom
C586  0.1uF/25V  [C0402]  208.51 110.83 0 bottom
C587  0.1uF/25V  [C0402]  204.54 110.84 0 bottom
C588  0.1uF/25V  [C0402]  202.51 110.86 180 bottom
C589  0.1uF/25V  [C0402]  202.53 107.84 0 bottom
C590  0.1uF/25V  [C0402]  202.53 106.84 0 bottom
C591  0.1uF/25V  [C0402]  222.69 105.66 180 bottom
C592  0.1uF/25V  [C0402]  222.54 109.82 180 bottom
C593  0.1uF/25V  [C0402]  219.6 105.79 180 bottom
C594  0.1uF/25V  [C0402]  218.05 106.35 90 bottom
C595  0.1uF/25V  [C0402]  216.04 107.34 90 bottom
C596  0.1uF/25V  [C0402]  225.54 107.84 180 bottom
C597  0.1uF/25V  [C0402]  226.56 109.84 0 bottom
C598  0.1uF/25V  [C0402]  220.56 108.84 0 bottom
C599  0.1uF/25V  [C0402]  226.56 111.83 0 bottom
C600  0.1uF/25V  [C0402]  218.56 108.85 0 bottom
C601  0.1uF/25V  [C0402]  216.55 109.83 0 bottom
C602  0.1uF/25V  [C0402]  230.54 111.84 0 bottom
C603  0.1uF/25V  [C0402]  250.69 108.55 270 bottom
C604  22uF/6.3V  [C0603]  241.64 105.62 0 top
C605  0.1uF/25V  [C0402]  199.56 112.84 0 bottom
C606  0.1uF/25V  [C0402]  199.56 114.84 0 bottom
C607  0.1uF/25V  [C0402]  211.56 114.84 180 bottom
C608  0.1uF/25V  [C0402]  195.56 114.84 0 bottom
C609  0.1uF/25V  [C0402]  202.52 112.82 0 bottom
C610  0.1uF/25V  [C0402]  202.56 114.83 0 bottom
C611  0.1uF/25V  [C0402]  220.54 112.85 0 bottom
C612  0.1uF/25V  [C0402]  224.07 111.33 270 bottom
C613  0.1uF/25V  [C0402]  222.54 111.83 180 bottom
C614  0.1uF/25V  [C0402]  230.57 115.84 0 bottom
C615  0.1uF/25V  [C0402]  218.54 111.83 0 bottom
C616  0.1uF/25V  [C0402]  222.57 115.85 0 bottom
C617  0.1uF/25V  [C0402]  224.55 112.88 0 bottom
C618  0.1uF/25V  [C0402]  229.55 113.81 0 bottom
C619  0.1uF/25V  [C0402]  228.54 115.84 180 bottom
C620  0.1uF/25V  [C0402]  208.56 113.84 180 bottom
C621  0.1uF/25V  [C0402]  195.56 112.84 0 bottom
C622  0.1uF/25V  [C0402]  205.56 114.84 180 bottom
C623  0.1uF/25V  [C0402]  205.56 113.84 0 bottom
C624  0.1uF/25V  [C0402]  211.56 112.84 180 bottom
C625  0.1uF/25V  [C0402]  211.56 116.84 180 bottom
C626  0.1uF/25V  [C0402]  208.56 114.84 180 bottom
C627  0.1uF/25V  [C0402]  218.58 115.85 0 bottom
C628  0.1uF/25V  [C0402]  220.54 114.83 180 bottom
C629  0.1uF/25V  [C0402]  224.56 114.85 0 bottom
C630  0.1uF/25V  [C0402]  249.97 119.74 90 bottom
C631  22uF/6.3V  [C0603]  241.64 107.13 0 top
C632  0.1uF/25V  [C0402]  229.56 117.83 0 bottom
C633  0.1uF/25V  [C0402]  199.56 118.84 0 bottom
C634  0.1uF/25V  [C0402]  211.56 118.84 180 bottom
C635  0.1uF/25V  [C0402]  208.56 116.84 180 bottom
C636  0.1uF/25V  [C0402]  199.56 116.84 0 bottom
C637  0.1uF/25V  [C0402]  205.56 116.84 180 bottom
C638  0.1uF/25V  [C0402]  217.53 117.83 180 bottom
C639  0.1uF/25V  [C0402]  202.56 118.84 0 bottom
C640  0.1uF/25V  [C0402]  225.54 117.85 180 bottom
C641  0.1uF/25V  [C0402]  224.57 120.85 0 bottom
C642  0.1uF/25V  [C0402]  217.53 120.85 180 bottom
C643  0.1uF/25V  [C0402]  222.57 117.85 180 bottom
C644  0.1uF/25V  [C0402]  226.54 123.85 0 bottom
C645  0.1uF/25V  [C0402]  223.56 123.85 180 bottom
C646  0.1uF/25V  [C0402]  230.57 123.85 0 bottom
C647  0.1uF/25V  [C0402]  208.56 118.84 180 bottom
C648  0.1uF/25V  [C0402]  205.56 118.84 180 bottom
C649  0.1uF/25V  [C0402]  202.56 116.84 0 bottom
C650  0.1uF/25V  [C0402]  226.56 121.83 0 bottom
C651  0.1uF/25V  [C0402]  226.56 119.83 0 bottom
C652  0.1uF/25V  [C0402]  220.54 120.85 0 bottom
C653  0.1uF/25V  [C0402]  222.57 120.85 0 bottom
C654  0.1uF/25V  [C0402]  222.54 118.86 0 bottom
C655  0.1uF/25V  [C0402]  220.54 117.85 0 bottom
C656  0.1uF/25V  [C0402]  223.59 124.88 0 bottom
C659  0.1uF/25V  [C0402]  230.57 125.83 0 bottom
C660  0.1uF/25V  [C0402]  227.56 129.82 0 bottom
C661  0.1uF/25V  [C0402]  227.53 131.82 0 bottom
C662  0.1uF/25V  [C0402]  221.55 133.85 180 bottom
C663  0.1uF/25V  [C0402]  223.56 132.85 0 bottom
C664  0.1uF/25V  [C0402]  217.54 132.85 180 bottom
C665  0.1uF/25V  [C0402]  219.56 132.85 180 bottom
C666  0.1uF/25V  [C0402]  229.05 126.36 90 bottom
C667  0.1uF/25V  [C0402]  217.53 127.84 180 bottom
C668  0.1uF/25V  [C0402]  221.56 126.85 0 bottom
C669  0.1uF/25V  [C0402]  223.56 126.85 0 bottom
C670  0.1uF/25V  [C0402]  229.55 129.87 0 bottom
C671  0.1uF/25V  [C0402]  223.55 135.85 0 bottom
C672  0.1uF/25V  [C0402]  227.55 133.82 0 bottom
C673  0.1uF/25V  [C0402]  221.55 135.82 180 bottom
C674  0.1uF/25V  [C0402]  223.56 133.85 0 bottom
C675  0.1uF/25V  [C0402]  229.55 127.88 0 bottom
C676  0.1uF/25V  [C0402]  223.52 130.85 180 bottom
C677  0.1uF/25V  [C0402]  225.54 135.86 180 bottom
C678  0.1uF/25V  [C0402]  219.57 129.84 180 bottom
C679  0.1uF/25V  [C0402]  217.56 129.84 180 bottom
C680  0.1uF/25V  [C0402]  225.56 126.85 0 bottom
C681  0.1uF/25V  [C0402]  219.54 123.83 0 bottom
C682  0.1uF/25V  [C0402]  227.57 135.84 0 bottom
C683  0.1uF/25V  [C0402]  221.54 123.85 0 bottom
C684  0.1uF/25V  [C0402]  251.9 146.56 0 bottom
C685  22uF/6.3V  [C0603]  242.86 137.82 270 bottom
C686  0.1uF/25V  [C0402]  217.5 139.81 180 bottom
C687  0.1uF/25V  [C0402]  230.54 148.8 0 bottom
C688  0.1uF/25V  [C0402]  223.56 148.84 0 bottom
C689  0.1uF/25V  [C0402]  219.54 139.78 180 bottom
C690  0.1uF/25V  [C0402]  223.55 139.81 180 bottom
C691  0.1uF/25V  [C0402]  221.54 139.77 180 bottom
C692  0.1uF/25V  [C0402]  221.54 143.86 180 bottom
C693  0.1uF/25V  [C0402]  229.57 135.84 0 bottom
C694  0.1uF/25V  [C0402]  229.58 137.84 0 bottom
C695  0.1uF/25V  [C0402]  227.56 146.86 0 bottom
C696  0.1uF/25V  [C0402]  221.54 145.85 0 bottom
C697  0.1uF/25V  [C0402]  223.54 145.82 0 bottom
C698  0.1uF/25V  [C0402]  223.54 146.82 0 bottom
C699  0.1uF/25V  [C0402]  221.54 148.84 180 bottom
C700  0.1uF/25V  [C0402]  229.54 142.83 0 bottom
C701  0.1uF/25V  [C0402]  229.54 140.83 0 bottom
C702  0.1uF/25V  [C0402]  219.53 143.83 180 bottom
C703  0.1uF/25V  [C0402]  223.54 143.84 180 bottom
C704  0.1uF/25V  [C0402]  217.55 135.82 180 bottom
C705  0.1uF/25V  [C0402]  219.55 135.82 180 bottom
C706  0.1uF/25V  [C0402]  217.53 143.83 180 bottom
C707  0.1uF/25V  [C0402]  225.54 144.85 180 bottom
C708  0.1uF/25V  [C0402]  219.52 145.85 0 bottom
C709  0.1uF/25V  [C0402]  225.58 143.86 180 bottom
C710  0.1uF/25V  [C0402]  227.5 148.84 0 bottom
C711  0.1uF/25V  [C0402]  252.34 153.39 270 bottom
C712  22uF/6.3V  [C0603]  245.05 149.1 0 bottom
C713  0.1uF/25V  [C0402]  225.56 151.84 0 bottom
C714  0.1uF/25V  [C0402]  230.54 150.8 0 bottom
C715  0.1uF/25V  [C0402]  208.04 160.33 90 bottom
C716  0.1uF/25V  [C0402]  206.03 160.35 90 bottom
C717  0.1uF/25V  [C0402]  211.04 160.34 270 bottom
C718  0.1uF/25V  [C0402]  219.56 151.84 0 bottom
C719  0.1uF/25V  [C0402]  228.54 150.8 180 bottom
C720  0.1uF/25V  [C0402]  217.54 148.84 180 bottom
C721  0.1uF/25V  [C0402]  226.56 158.83 0 bottom
C722  0.1uF/25V  [C0402]  223.54 158.84 180 bottom
C723  0.1uF/25V  [C0402]  225.54 160.86 180 bottom
C724  0.1uF/25V  [C0402]  223.57 154.84 180 bottom
C725  0.1uF/25V  [C0402]  221.54 155.83 180 bottom
C726  0.1uF/25V  [C0402]  230.57 152.91 0 bottom
C727  0.1uF/25V  [C0402]  219.56 154.84 0 bottom
C728  0.1uF/25V  [C0402]  229.58 154.84 0 bottom
C729  0.1uF/25V  [C0402]  221.56 151.84 0 bottom
C730  0.1uF/25V  [C0402]  219.54 148.84 180 bottom
C731  0.1uF/25V  [C0402]  227.58 154.84 0 bottom
C732  0.1uF/25V  [C0402]  223.56 157.84 0 bottom
C733  0.1uF/25V  [C0402]  221.52 157.84 0 bottom
C734  0.1uF/25V  [C0402]  219.52 157.84 0 bottom
C735  0.1uF/25V  [C0402]  226.56 156.84 180 bottom
C736  0.1uF/25V  [C0402]  221.56 154.84 0 bottom
C737  0.1uF/25V  [C0402]  223.56 151.84 0 bottom
C738  0.1uF/25V  [C0402]  252.54 166.49 90 bottom
C739  22uF/6.3V  [C0603]  244.67 162.18 270 bottom
C740  0.1uF/25V  [C0402]  216.08 165.33 90 bottom
C741  0.1uF/25V  [C0402]  215.53 161.84 180 bottom
C742  0.1uF/25V  [C0402]  214.05 164.33 90 bottom
C743  0.1uF/25V  [C0402]  205.06 163.33 270 bottom
C744  0.1uF/25V  [C0402]  204.53 161.84 180 bottom
C745  0.1uF/25V  [C0402]  208.05 162.33 90 bottom
C746  0.1uF/25V  [C0402]  208.04 164.33 90 bottom
C747  0.1uF/25V  [C0402]  212.05 165.35 90 bottom
C870  47uF/6.3V  [C0805]  257.11 161.8 0 top
C871  47uF/6.3V  [C0805]  257.11 157.22 0 top
C872  47uF/6.3V  [C0805]  257.11 152.65 0 top
C873  47uF/6.3V  [C0805]  257.11 145.79 0 top
C874  47uF/6.3V  [C0805]  257.11 141.22 0 top
C875  47uF/6.3V  [C0805]  257.11 136.65 0 top
C876  47uF/6.3V  [C0805]  257.11 132.08 0 top
C877  47uF/6.3V  [C0805]  257.11 127.51 0 top
C878  10uF/6.3V  [C0402]  209.55 128.82 0 bottom
C879  10uF/6.3V  [C0402]  203.54 128.83 0 bottom
C882  10uF/6.3V  [C0402]  205.55 127.82 0 bottom
C883  10uF/6.3V  [C0402]  209.55 149.82 180 bottom
C884  10uF/6.3V  [C0402]  207.55 140.82 0 bottom
C885  10uF/6.3V  [C0402]  207.55 150.82 0 bottom
C886  10uF/6.3V  [C0402]  199.54 131.83 0 bottom
C887  10uF/6.3V  [C0402]  207.55 131.82 0 bottom
C923  10uF/6.3V  [C0402]  201.54 144.83 0 bottom
C924  10uF/6.3V  [C0402]  207.55 142.82 0 bottom
C925  10uF/6.3V  [C0402]  203.54 141.83 0 bottom
C926  10uF/6.3V  [C0402]  199.54 147.83 0 bottom
C927  10uF/6.3V  [C0402]  207.55 144.82 0 bottom
C928  10uF/6.3V  [C0402]  205.55 142.82 0 bottom
C929  10uF/6.3V  [C0402]  199.54 133.83 0 bottom
C930  10uF/6.3V  [C0402]  199.54 146.83 0 bottom
C931  10uF/6.3V  [C0402]  205.55 140.82 0 bottom
C932  10uF/6.3V  [C0402]  201.54 143.83 0 bottom
C933  10uF/6.3V  [C0402]  207.55 141.82 0 bottom
C934  10uF/6.3V  [C0402]  203.54 133.83 0 bottom
C935  10uF/6.3V  [C0402]  199.54 145.83 180 bottom
C936  10uF/6.3V  [C0402]  207.55 151.82 180 bottom
C937  10uF/6.3V  [C0402]  205.55 149.82 0 bottom
C938  10uF/6.3V  [C0402]  203.54 140.83 0 bottom
C939  10uF/6.3V  [C0402]  201.54 148.83 0 bottom
C940  10uF/6.3V  [C0402]  205.55 148.82 0 bottom
C941  10uF/6.3V  [C0402]  203.54 151.83 180 bottom
C942  10uF/6.3V  [C0402]  201.54 147.83 0 bottom
C943  10uF/6.3V  [C0402]  199.54 137.83 0 bottom
C944  10uF/6.3V  [C0402]  197.55 136.84 180 bottom
C945  10uF/6.3V  [C0402]  199.54 151.83 180 bottom
C946  10uF/6.3V  [C0402]  201.54 133.83 0 bottom
C947  10uF/6.3V  [C0402]  201.54 129.83 0 bottom
C948  10uF/6.3V  [C0402]  201.54 131.83 0 bottom
C957  10uF/6.3V  [C0402]  191.55 130.83 0 bottom
C958  10uF/6.3V  [C0402]  195.55 130.83 0 bottom
C959  10uF/6.3V  [C0402]  195.55 137.84 0 bottom
C960  10uF/6.3V  [C0402]  183.55 135.83 0 bottom
C961  10uF/6.3V  [C0402]  183.55 133.83 0 bottom
C962  10uF/6.3V  [C0402]  195.55 133.83 0 bottom
C963  10uF/6.3V  [C0402]  195.55 129.83 0 bottom
C964  10uF/6.3V  [C0402]  195.55 132.83 0 bottom
C965  10uF/6.3V  [C0402]  185.55 136.83 0 bottom
C966  10uF/6.3V  [C0402]  193.55 127.83 0 bottom
C967  10uF/6.3V  [C0402]  191.55 136.83 0 bottom
C968  10uF/6.3V  [C0402]  187.55 136.83 0 bottom
C969  10uF/6.3V  [C0402]  193.55 132.83 0 bottom
C970  10uF/6.3V  [C0402]  187.55 134.83 0 bottom
C971  10uF/6.3V  [C0402]  195.55 128.83 0 bottom
C972  10uF/6.3V  [C0402]  193.55 135.83 0 bottom
C973  10uF/6.3V  [C0402]  193.55 130.83 0 bottom
C974  10uF/6.3V  [C0402]  191.55 129.83 0 bottom
C975  10uF/6.3V  [C0402]  189.54 151.83 180 bottom
C976  10uF/6.3V  [C0402]  183.55 136.83 0 bottom
C977  10uF/6.3V  [C0402]  193.55 141.82 0 bottom
C978  10uF/6.3V  [C0402]  185.55 134.83 0 bottom
C979  10uF/6.3V  [C0402]  189.55 132.83 0 bottom
C980  10uF/6.3V  [C0402]  193.55 133.83 0 bottom
C981  10uF/6.3V  [C0402]  191.55 132.83 0 bottom
C982  10uF/6.3V  [C0402]  187.55 133.83 0 bottom
C983  10uF/6.3V  [C0402]  189.55 135.83 0 bottom
C984  10uF/6.3V  [C0402]  189.55 134.83 0 bottom
C985  10uF/6.3V  [C0402]  191.55 134.83 0 bottom
C986  10uF/6.3V  [C0402]  193.55 136.83 0 bottom
C987  10uF/6.3V  [C0402]  193.55 142.82 180 bottom
C988  10uF/6.3V  [C0402]  191.55 133.83 0 bottom
C989  10uF/6.3V  [C0402]  191.55 137.83 0 bottom
C990  10uF/6.3V  [C0402]  185.55 135.83 0 bottom
C991  10uF/6.3V  [C0402]  195.55 134.83 0 bottom
C992  10uF/6.3V  [C0402]  191.55 135.83 0 bottom
C993  10uF/6.3V  [C0402]  193.55 126.83 0 bottom
C994  10uF/6.3V  [C0402]  195.55 131.83 0 bottom
C995  10uF/6.3V  [C0402]  195.55 136.83 0 bottom
C996  10uF/6.3V  [C0402]  197.55 137.84 0 bottom
C997  10uF/6.3V  [C0402]  185.55 137.83 0 bottom
C998  10uF/6.3V  [C0402]  187.55 137.83 0 bottom
C999  10uF/6.3V  [C0402]  189.55 137.83 0 bottom
C1000  10uF/6.3V  [C0402]  191.55 141.82 0 bottom
C1001  10uF/6.3V  [C0402]  191.55 142.82 180 bottom
C1002  10uF/6.3V  [C0402]  189.55 144.82 0 bottom
C1003  10uF/6.3V  [C0402]  189.55 143.82 0 bottom
C1004  10uF/6.3V  [C0402]  187.54 141.83 0 bottom
C1005  10uF/6.3V  [C0402]  195.55 148.82 0 bottom
C1006  10uF/6.3V  [C0402]  183.54 141.83 180 bottom
C1007  10uF/6.3V  [C0402]  185.54 140.83 0 bottom
C1008  10uF/6.3V  [C0402]  183.54 140.83 0 bottom
C1009  10uF/6.3V  [C0402]  191.55 145.82 0 bottom
C1010  10uF/6.3V  [C0402]  191.55 140.82 180 bottom
C1011  10uF/6.3V  [C0402]  191.55 144.82 0 bottom
C1012  10uF/6.3V  [C0402]  189.55 142.82 0 bottom
C1013  10uF/6.3V  [C0402]  187.54 140.83 0 bottom
C1014  10uF/6.3V  [C0402]  183.54 147.83 0 bottom
C1015  10uF/6.3V  [C0402]  193.55 144.82 0 bottom
C1016  10uF/6.3V  [C0402]  193.55 145.82 0 bottom
C1017  10uF/6.3V  [C0402]  193.55 143.82 0 bottom
C1018  10uF/6.3V  [C0402]  195.55 150.82 180 bottom
C1019  10uF/6.3V  [C0402]  195.55 149.82 180 bottom
C1020  10uF/6.3V  [C0402]  185.54 150.83 0 bottom
C1021  10uF/6.3V  [C0402]  193.55 147.82 0 bottom
C1022  10uF/6.3V  [C0402]  183.54 148.83 180 bottom
C1023  10uF/6.3V  [C0402]  187.54 150.83 0 bottom
C1024  10uF/6.3V  [C0402]  191.55 149.82 0 bottom
C1025  10uF/6.3V  [C0402]  183.54 144.83 0 bottom
C1026  10uF/6.3V  [C0402]  183.54 145.83 180 bottom
C1027  10uF/6.3V  [C0402]  183.54 146.83 0 bottom
C1028  10uF/6.3V  [C0402]  185.54 145.83 180 bottom
C1029  10uF/6.3V  [C0402]  193.55 150.82 0 bottom
C1030  10uF/6.3V  [C0402]  185.54 151.83 180 bottom
C1031  10uF/6.3V  [C0402]  185.54 146.83 0 bottom
C1032  10uF/6.3V  [C0402]  185.54 148.83 0 bottom
C1033  10uF/6.3V  [C0402]  185.54 147.83 0 bottom
C1034  10uF/6.3V  [C0402]  191.55 151.82 180 bottom
C1035  10uF/6.3V  [C0402]  187.54 147.83 0 bottom
C1036  10uF/6.3V  [C0402]  191.55 150.82 0 bottom
C1037  10uF/6.3V  [C0402]  183.54 150.83 0 bottom
C1038  10uF/6.3V  [C0402]  187.54 151.83 180 bottom
C1039  10uF/6.3V  [C0402]  189.55 147.82 0 bottom
C1040  10uF/6.3V  [C0402]  187.54 148.83 0 bottom
C1041  10uF/6.3V  [C0402]  187.54 144.83 0 bottom
C1042  10uF/6.3V  [C0402]  189.55 150.82 0 bottom
C1043  10uF/6.3V  [C0402]  195.55 147.82 180 bottom
C1044  10uF/6.3V  [C0402]  183.54 151.83 180 bottom
C1045  10uF/6.3V  [C0402]  207.55 129.82 0 bottom
C1046  10uF/6.3V  [C0402]  201.54 128.83 0 bottom
C1047  10uF/6.3V  [C0402]  201.54 151.83 180 bottom
C1048  10uF/6.3V  [C0402]  203.54 126.83 0 bottom
C1049  10uF/6.3V  [C0402]  209.55 150.82 0 bottom
C1050  10uF/6.3V  [C0402]  201.54 150.83 0 bottom
C1051  10uF/6.3V  [C0402]  207.55 135.82 0 bottom
C1143  0.1uF/25V  [C0402]  202.05 154.34 90 bottom
C1144  10uF/6.3V  [C0402]  185.55 126.83 0 bottom
C1145  10uF/6.3V  [C0402]  209.55 137.82 0 bottom
C1146  10uF/6.3V  [C0402]  185.54 144.83 0 bottom
C1147  10uF/6.3V  [C0402]  189.55 141.82 0 bottom
C1148  10uF/6.3V  [C0402]  187.55 130.83 0 bottom
C1149  10uF/6.3V  [C0402]  193.55 137.83 0 bottom
C1150  10uF/6.3V  [C0402]  187.55 127.83 0 bottom
C1151  10uF/6.3V  [C0402]  199.54 126.83 180 bottom
C1152  10uF/6.3V  [C0402]  187.54 146.83 0 bottom
C1153  10uF/6.3V  [C0402]  189.55 131.83 0 bottom
C1154  10uF/6.3V  [C0402]  193.55 128.83 0 bottom
C1155  10uF/6.3V  [C0402]  189.55 126.83 0 bottom
C1156  10uF/6.3V  [C0402]  197.55 133.83 0 bottom
C1157  10uF/6.3V  [C0402]  183.55 129.83 0 bottom
C1158  10uF/6.3V  [C0402]  189.55 148.82 0 bottom
C1159  10uF/6.3V  [C0402]  191.55 126.83 0 bottom
C1160  10uF/6.3V  [C0402]  187.55 131.83 0 bottom
C1161  10uF/6.3V  [C0402]  187.55 129.83 0 bottom
C1162  10uF/6.3V  [C0402]  197.55 135.83 0 bottom
C1163  10uF/6.3V  [C0402]  187.54 142.83 0 bottom
C1164  10uF/6.3V  [C0402]  189.55 146.82 0 bottom
C1165  10uF/6.3V  [C0402]  187.55 135.83 0 bottom
C1166  10uF/6.3V  [C0402]  197.55 129.83 0 bottom
C1167  10uF/6.3V  [C0402]  191.55 127.83 0 bottom
C1168  10uF/6.3V  [C0402]  183.55 131.83 0 bottom
C1169  10uF/6.3V  [C0402]  185.55 128.83 0 bottom
C1170  10uF/6.3V  [C0402]  189.55 133.83 0 bottom
C1171  10uF/6.3V  [C0402]  187.55 132.83 0 bottom
C1172  10uF/6.3V  [C0402]  189.55 128.83 0 bottom
C1173  10uF/6.3V  [C0402]  193.55 149.82 0 bottom
C1174  10uF/6.3V  [C0402]  197.55 131.83 0 bottom
C1175  10uF/6.3V  [C0402]  185.55 132.83 0 bottom
C1176  10uF/6.3V  [C0402]  189.55 129.83 0 bottom
C1177  10uF/6.3V  [C0402]  189.55 149.82 0 bottom
C1178  10uF/6.3V  [C0402]  189.55 145.82 0 bottom
C1179  10uF/6.3V  [C0402]  191.55 147.82 0 bottom
C1180  10uF/6.3V  [C0402]  189.55 130.83 0 bottom
C1181  10uF/6.3V  [C0402]  191.55 131.83 0 bottom
C1182  10uF/6.3V  [C0402]  185.55 130.83 0 bottom
C1183  10uF/6.3V  [C0402]  189.55 127.83 0 bottom
C1184  10uF/6.3V  [C0402]  185.55 129.83 0 bottom
C1185  10uF/6.3V  [C0402]  187.55 126.83 0 bottom
C1186  10uF/6.3V  [C0402]  185.55 127.83 0 bottom
C1187  10uF/6.3V  [C0402]  183.55 127.83 0 bottom
C1188  10uF/6.3V  [C0402]  191.55 128.83 0 bottom
C1189  10uF/6.3V  [C0402]  191.55 148.82 0 bottom
C1190  10uF/6.3V  [C0402]  187.54 145.83 0 bottom
C1191  10uF/6.3V  [C0402]  195.55 127.83 0 bottom
C1192  10uF/6.3V  [C0402]  187.55 128.83 0 bottom
C1193  10uF/6.3V  [C0402]  185.55 131.83 0 bottom
C1194  10uF/6.3V  [C0402]  209.55 136.82 180 bottom
C1195  10uF/6.3V  [C0402]  209.55 134.82 0 bottom
C1196  10uF/6.3V  [C0402]  209.55 132.82 0 bottom
C1197  10uF/6.3V  [C0402]  209.55 148.82 0 bottom
C1198  10uF/6.3V  [C0402]  209.55 147.82 0 bottom
C1199  10uF/6.3V  [C0402]  209.55 146.82 0 bottom
C1200  10uF/6.3V  [C0402]  209.55 145.82 0 bottom
C1201  10uF/6.3V  [C0402]  209.55 144.82 0 bottom
C1202  10uF/6.3V  [C0402]  209.55 143.82 0 bottom
C1203  10uF/6.3V  [C0402]  209.55 142.82 0 bottom
C1204  10uF/6.3V  [C0402]  209.55 141.82 0 bottom
C1205  10uF/6.3V  [C0402]  209.55 140.82 0 bottom
C1206  10uF/6.3V  [C0402]  199.54 130.83 0 bottom
C1207  10uF/6.3V  [C0402]  211.55 137.82 0 bottom
C1208  10uF/6.3V  [C0402]  211.55 136.82 180 bottom
C1209  10uF/6.3V  [C0402]  211.55 135.82 0 bottom
C1210  10uF/6.3V  [C0402]  211.55 134.82 180 bottom
C1211  10uF/6.3V  [C0402]  211.55 133.82 0 bottom
C1212  10uF/6.3V  [C0402]  211.55 132.82 180 bottom
C1213  10uF/6.3V  [C0402]  211.55 131.82 0 bottom
C1214  10uF/6.3V  [C0402]  211.55 130.82 180 bottom
C1215  10uF/6.3V  [C0402]  211.55 129.82 0 bottom
C1216  10uF/6.3V  [C0402]  211.55 128.82 180 bottom
C1217  10uF/6.3V  [C0402]  209.55 131.82 0 bottom
C1218  10uF/6.3V  [C0402]  209.55 130.82 0 bottom
C1219  10uF/6.3V  [C0402]  209.55 129.82 0 bottom
C1220  10uF/6.3V  [C0402]  201.54 149.83 0 bottom
C1221  10uF/6.3V  [C0402]  203.54 149.83 0 bottom
C1222  10uF/6.3V  [C0402]  189.55 140.82 180 bottom
C1223  10uF/6.3V  [C0402]  203.54 150.83 0 bottom
C1224  10uF/6.3V  [C0402]  203.54 148.83 0 bottom
C1225  10uF/6.3V  [C0402]  203.54 147.83 0 bottom
C1226  10uF/6.3V  [C0402]  203.54 146.83 0 bottom
C1227  10uF/6.3V  [C0402]  203.54 145.83 0 bottom
C1228  10uF/6.3V  [C0402]  203.54 144.83 0 bottom
C1229  10uF/6.3V  [C0402]  203.54 143.83 0 bottom
C1230  10uF/6.3V  [C0402]  203.54 142.83 0 bottom
C1231  10uF/6.3V  [C0402]  201.54 127.83 0 bottom
C1232  10uF/6.3V  [C0402]  199.54 143.83 180 bottom
C1233  10uF/6.3V  [C0402]  201.54 141.83 0 bottom
C1234  10uF/6.3V  [C0402]  193.55 140.82 180 bottom
C1235  10uF/6.3V  [C0402]  195.55 140.82 180 bottom
C1236  10uF/6.3V  [C0402]  195.55 146.82 0 bottom
C1237  10uF/6.3V  [C0402]  199.54 149.83 0 bottom
C1238  10uF/6.3V  [C0402]  205.54 151.83 180 bottom
C1239  10uF/6.3V  [C0402]  205.55 150.82 0 bottom
C1240  10uF/6.3V  [C0402]  205.55 141.82 0 bottom
C1241  10uF/6.3V  [C0402]  203.54 136.83 180 bottom
C1242  10uF/6.3V  [C0402]  205.55 136.82 180 bottom
C1243  10uF/6.3V  [C0402]  205.55 134.82 0 bottom
C1244  10uF/6.3V  [C0402]  205.55 131.82 0 bottom
C1245  10uF/6.3V  [C0402]  199.54 128.83 0 bottom
C1246  10uF/6.3V  [C0402]  205.55 128.82 0 bottom
C1247  10uF/6.3V  [C0402]  195.55 145.82 180 bottom
C1248  10uF/6.3V  [C0402]  195.55 144.82 0 bottom
C1249  10uF/6.3V  [C0402]  191.55 139.82 0 bottom
C1250  10uF/6.3V  [C0402]  195.55 143.82 180 bottom
C1251  10uF/6.3V  [C0402]  195.55 141.82 180 bottom
C1252  10uF/6.3V  [C0402]  189.55 139.82 0 bottom
C1253  10uF/6.3V  [C0402]  195.55 142.82 180 bottom
C1254  10uF/6.3V  [C0402]  185.54 143.83 0 bottom
C1255  10uF/6.3V  [C0402]  193.55 139.82 0 bottom
C1256  10uF/6.3V  [C0402]  209.55 135.82 0 bottom
C1257  10uF/6.3V  [C0402]  209.55 133.82 0 bottom
C1258  10uF/6.3V  [C0402]  211.55 151.82 180 bottom
C1259  10uF/6.3V  [C0402]  211.55 150.82 0 bottom
C1260  10uF/6.3V  [C0402]  211.55 149.82 180 bottom
C1261  10uF/6.3V  [C0402]  211.55 148.82 0 bottom
